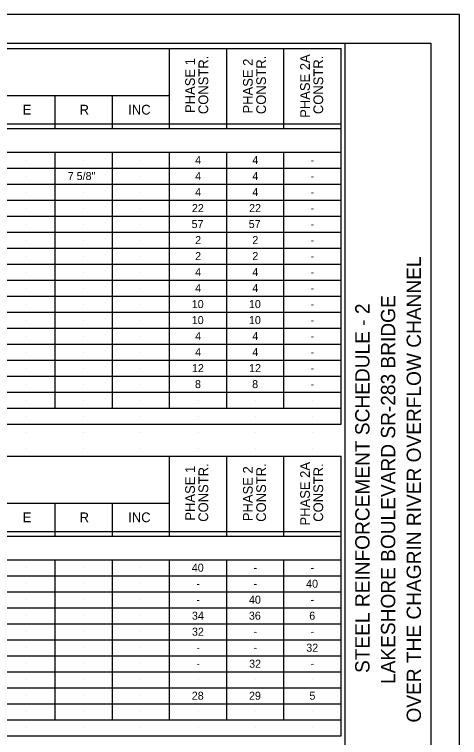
# Model space of a CAD drawing. Extents: x 0 to 34, y 0 to 22.
# Drawn here: x 26.21 to 34, y 9.35 to 22 of the extents above; entities that cross this region are included whole.
import ezdxf

# ---------------------------------------------------------------- set-up
doc = ezdxf.new("R2010")
doc.units = 0
for name, color, linetype in [('BR_P_Gen_Text', 7, 'Continuous'), ('SH_Border', 7, 'Continuous'), ('SH_Cut_Line', 7, 'Continuous'), ('SH_Data', 7, 'Continuous')]:
    doc.layers.add(name, color=color, linetype=linetype)

msp = doc.modelspace()

# ---------------------------------------------------------------- linework, layer by layer
at = {"layer": 'BR_P_Gen_Text'}
for p, q in [((16.76, 21.404), (31.927, 21.404)), ((28.927, 20.004), (28.927, 21.404)), ((29.927, 20.004), (29.927, 21.404)), ((30.927, 20.004), (30.927, 21.404)), ((31.927, 14.833), (31.927, 21.404)), ((21.927, 20.581), (28.927, 20.581)), ((26.927, 20.004), (26.927, 20.581)), ((27.927, 20.004), (27.927, 20.581)), ((16.76, 20.087), (31.927, 20.087)), ((16.76, 20.004), (31.927, 20.004)), ((16.76, 19.593), (31.927, 19.593)), ((26.927, 15.113), (26.927, 19.593)), ((27.927, 15.113), (27.927, 19.593)), ((28.927, 15.113), (28.927, 19.593)), ((29.927, 15.113), (29.927, 19.593)), ((30.927, 15.113), (30.927, 19.593)), ((26.427, 19.453), (26.427, 19.453)), ((27.427, 19.453), (27.427, 19.453)), ((28.427, 19.453), (28.427, 19.453)), ((29.427, 19.453), (29.427, 19.453)), ((30.427, 19.453), (30.427, 19.453)), ((31.427, 19.453), (31.427, 19.453)), ((16.76, 19.313), (31.927, 19.313)), ((26.427, 19.173), (26.427, 19.173)), ((27.427, 19.173), (27.427, 19.173)), ((28.427, 19.173), (28.427, 19.173)), ((29.427, 19.173), (29.427, 19.173)), ((30.427, 19.173), (30.427, 19.173)), ((31.427, 19.173), (31.427, 19.173)), ((16.76, 19.033), (31.927, 19.033)), ((26.427, 18.893), (26.427, 18.893)), ((27.427, 18.893), (27.427, 18.893)), ((28.427, 18.893), (28.427, 18.893)), ((29.427, 18.893), (29.427, 18.893)), ((30.427, 18.893), (30.427, 18.893)), ((31.427, 18.893), (31.427, 18.893)), ((16.76, 18.753), (31.927, 18.753)), ((26.427, 18.613), (26.427, 18.613)), ((27.427, 18.613), (27.427, 18.613)), ((28.427, 18.613), (28.427, 18.613)), ((29.427, 18.613), (29.427, 18.613)), ((30.427, 18.613), (30.427, 18.613)), ((31.427, 18.613), (31.427, 18.613)), ((16.76, 18.473), (31.927, 18.473)), ((26.427, 18.333), (26.427, 18.333)), ((27.427, 18.333), (27.427, 18.333)), ((28.427, 18.333), (28.427, 18.333)), ((29.427, 18.333), (29.427, 18.333)), ((30.427, 18.333), (30.427, 18.333)), ((31.427, 18.333), (31.427, 18.333)), ((16.76, 18.193), (31.927, 18.193)), ((26.427, 18.053), (26.427, 18.053)), ((27.427, 18.053), (27.427, 18.053)), ((28.427, 18.053), (28.427, 18.053)), ((29.427, 18.053), (29.427, 18.053)), ((30.427, 18.053), (30.427, 18.053)), ((31.427, 18.053), (31.427, 18.053)), ((16.76, 17.913), (31.927, 17.913)), ((26.427, 17.773), (26.427, 17.773)), ((27.427, 17.773), (27.427, 17.773)), ((28.427, 17.773), (28.427, 17.773)), ((29.427, 17.773), (29.427, 17.773)), ((30.427, 17.773), (30.427, 17.773)), ((31.427, 17.773), (31.427, 17.773)), ((16.76, 17.633), (31.927, 17.633)), ((26.427, 17.493), (26.427, 17.493)), ((26.427, 17.493), (26.427, 17.493)), ((27.427, 17.493), (27.427, 17.493)), ((27.427, 17.493), (27.427, 17.493)), ((28.427, 17.493), (28.427, 17.493)), ((28.427, 17.493), (28.427, 17.493)), ((29.427, 17.493), (29.427, 17.493)), ((30.427, 17.493), (30.427, 17.493)), ((31.427, 17.493), (31.427, 17.493)), ((16.76, 17.353), (31.927, 17.353)), ((26.427, 17.213), (26.427, 17.213)), ((26.427, 17.213), (26.427, 17.213)), ((27.427, 17.213), (27.427, 17.213)), ((27.427, 17.213), (27.427, 17.213)), ((28.427, 17.213), (28.427, 17.213)), ((28.427, 17.213), (28.427, 17.213)), ((29.427, 17.213), (29.427, 17.213)), ((29.427, 17.213), (29.427, 17.213)), ((30.427, 17.213), (30.427, 17.213)), ((30.427, 17.213), (30.427, 17.213)), ((31.427, 17.213), (31.427, 17.213)), ((31.427, 17.213), (31.427, 17.213)), ((16.76, 17.073), (31.927, 17.073)), ((26.427, 16.933), (26.427, 16.933)), ((27.427, 16.933), (27.427, 16.933)), ((28.427, 16.933), (28.427, 16.933)), ((29.427, 16.933), (29.427, 16.933)), ((30.427, 16.933), (30.427, 16.933)), ((31.427, 16.933), (31.427, 16.933)), ((16.76, 16.793), (31.927, 16.793)), ((26.427, 16.653), (26.427, 16.653)), ((27.427, 16.653), (27.427, 16.653)), ((28.427, 16.653), (28.427, 16.653)), ((29.427, 16.653), (29.427, 16.653)), ((30.427, 16.653), (30.427, 16.653)), ((31.427, 16.653), (31.427, 16.653)), ((16.76, 16.513), (31.927, 16.513)), ((26.427, 16.373), (26.427, 16.373)), ((27.427, 16.373), (27.427, 16.373)), ((28.427, 16.373), (28.427, 16.373)), ((29.427, 16.373), (29.427, 16.373)), ((30.427, 16.373), (30.427, 16.373)), ((31.427, 16.373), (31.427, 16.373)), ((16.76, 16.233), (31.927, 16.233)), ((26.427, 16.093), (26.427, 16.093)), ((27.427, 16.093), (27.427, 16.093)), ((28.427, 16.093), (28.427, 16.093)), ((29.427, 16.093), (29.427, 16.093)), ((30.427, 16.093), (30.427, 16.093)), ((31.427, 16.093), (31.427, 16.093)), ((16.76, 15.953), (31.927, 15.953)), ((26.427, 15.813), (26.427, 15.813)), ((27.427, 15.813), (27.427, 15.813)), ((28.427, 15.813), (28.427, 15.813)), ((29.427, 15.813), (29.427, 15.813)), ((30.427, 15.813), (30.427, 15.813)), ((31.427, 15.813), (31.427, 15.813)), ((16.76, 15.673), (31.927, 15.673)), ((26.427, 15.533), (26.427, 15.533)), ((27.427, 15.533), (27.427, 15.533)), ((28.427, 15.533), (28.427, 15.533)), ((29.427, 15.533), (29.427, 15.533)), ((30.427, 15.533), (30.427, 15.533)), ((31.427, 15.533), (31.427, 15.533)), ((16.76, 15.393), (31.927, 15.393)), ((26.427, 15.253), (26.427, 15.253)), ((27.427, 15.253), (27.427, 15.253)), ((28.427, 15.253), (28.427, 15.253)), ((29.427, 15.253), (29.427, 15.253)), ((30.427, 15.253), (30.427, 15.253)), ((31.427, 15.253), (31.427, 15.253)), ((16.76, 15.113), (31.927, 15.113)), ((26.427, 14.973), (26.427, 14.973)), ((27.427, 14.973), (27.427, 14.973)), ((28.427, 14.973), (28.427, 14.973)), ((29.427, 14.973), (29.427, 14.973)), ((30.427, 14.973), (30.427, 14.973)), ((31.427, 14.973), (31.427, 14.973)), ((16.76, 14.833), (31.927, 14.833)), ((26.427, 14.693), (26.427, 14.693)), ((26.427, 14.693), (26.427, 14.693)), ((27.427, 14.693), (27.427, 14.693)), ((27.427, 14.693), (27.427, 14.693)), ((28.427, 14.693), (28.427, 14.693)), ((28.427, 14.693), (28.427, 14.693)), ((29.427, 14.693), (29.427, 14.693)), ((30.427, 14.693), (30.427, 14.693)), ((31.427, 14.693), (31.427, 14.693)), ((26.427, 14.413), (26.427, 14.413)), ((27.427, 14.413), (27.427, 14.413)), ((28.427, 14.413), (28.427, 14.413)), ((29.427, 14.413), (29.427, 14.413)), ((30.427, 14.413), (30.427, 14.413)), ((31.427, 14.413), (31.427, 14.413)), ((16.76, 14.272), (31.927, 14.273)), ((28.927, 12.872), (28.927, 14.273)), ((29.927, 12.872), (29.927, 14.273)), ((30.927, 12.872), (30.927, 14.273)), ((31.927, 9.381), (31.927, 14.273)), ((21.927, 13.449), (28.927, 13.449)), ((26.927, 12.872), (26.927, 13.449)), ((27.927, 12.872), (27.927, 13.449)), ((16.76, 12.955), (31.927, 12.955)), ((16.76, 12.872), (31.927, 12.872)), ((16.76, 12.461), (31.927, 12.461)), ((26.927, 9.661), (26.927, 12.461)), ((27.927, 9.661), (27.927, 12.461)), ((28.927, 9.661), (28.927, 12.461)), ((29.927, 9.661), (29.927, 12.461)), ((30.927, 9.661), (30.927, 12.461)), ((26.427, 12.321), (26.427, 12.321)), ((27.427, 12.321), (27.427, 12.321)), ((28.427, 12.321), (28.427, 12.321)), ((29.427, 12.321), (29.427, 12.321)), ((30.427, 12.321), (30.427, 12.321)), ((31.427, 12.321), (31.427, 12.321)), ((16.76, 12.181), (31.927, 12.181)), ((26.427, 12.041), (26.427, 12.041)), ((27.427, 12.041), (27.427, 12.041)), ((28.427, 12.041), (28.427, 12.041)), ((29.427, 12.041), (29.427, 12.041)), ((30.427, 12.041), (30.427, 12.041)), ((31.427, 12.041), (31.427, 12.041)), ((16.76, 11.901), (31.927, 11.901)), ((26.427, 11.761), (26.427, 11.761)), ((27.427, 11.761), (27.427, 11.761)), ((28.427, 11.761), (28.427, 11.761)), ((30.427, 11.761), (30.427, 11.761)), ((31.427, 11.761), (31.427, 11.761)), ((16.76, 11.621), (31.927, 11.621)), ((26.427, 11.481), (26.427, 11.481)), ((27.427, 11.481), (27.427, 11.481)), ((28.427, 11.481), (28.427, 11.481)), ((29.427, 11.481), (29.427, 11.481)), ((30.427, 11.481), (30.427, 11.481)), ((31.427, 11.481), (31.427, 11.481)), ((16.76, 11.341), (31.927, 11.341)), ((26.427, 11.201), (26.427, 11.201)), ((27.427, 11.201), (27.427, 11.201)), ((28.427, 11.201), (28.427, 11.201)), ((29.427, 11.201), (29.427, 11.201)), ((30.427, 11.201), (30.427, 11.201)), ((31.427, 11.201), (31.427, 11.201)), ((16.76, 11.061), (31.927, 11.061)), ((26.427, 10.921), (26.427, 10.921)), ((27.427, 10.921), (27.427, 10.921)), ((28.427, 10.921), (28.427, 10.921)), ((29.427, 10.921), (29.427, 10.921)), ((30.427, 10.921), (30.427, 10.921)), ((31.427, 10.921), (31.427, 10.921)), ((16.76, 10.781), (31.927, 10.781)), ((26.427, 10.641), (26.427, 10.641)), ((27.427, 10.641), (27.427, 10.641)), ((28.427, 10.641), (28.427, 10.641)), ((29.427, 10.641), (29.427, 10.641)), ((30.427, 10.641), (30.427, 10.641)), ((31.427, 10.641), (31.427, 10.641)), ((16.76, 10.501), (31.927, 10.501)), ((26.427, 10.361), (26.427, 10.361)), ((26.427, 10.361), (26.427, 10.361)), ((27.427, 10.361), (27.427, 10.361)), ((27.427, 10.361), (27.427, 10.361)), ((28.427, 10.361), (28.427, 10.361)), ((28.427, 10.361), (28.427, 10.361)), ((29.427, 10.361), (29.427, 10.361)), ((30.427, 10.361), (30.427, 10.361)), ((31.427, 10.361), (31.427, 10.361)), ((16.76, 10.221), (31.927, 10.221)), ((26.427, 10.081), (26.427, 10.081)), ((26.427, 10.081), (26.427, 10.081)), ((27.427, 10.081), (27.427, 10.081)), ((27.427, 10.081), (27.427, 10.081)), ((28.427, 10.081), (28.427, 10.081)), ((28.427, 10.081), (28.427, 10.081)), ((29.427, 10.081), (29.427, 10.081)), ((29.427, 10.081), (29.427, 10.081)), ((30.427, 10.081), (30.427, 10.081)), ((30.427, 10.081), (30.427, 10.081)), ((31.427, 10.081), (31.427, 10.081)), ((31.427, 10.081), (31.427, 10.081)), ((16.76, 9.941), (31.927, 9.941)), ((26.427, 9.801), (26.427, 9.801)), ((27.427, 9.801), (27.427, 9.801)), ((28.427, 9.801), (28.427, 9.801)), ((29.427, 9.801), (29.427, 9.801)), ((30.427, 9.801), (30.427, 9.801)), ((31.427, 9.801), (31.427, 9.801)), ((16.76, 9.661), (31.927, 9.661)), ((26.427, 9.521), (26.427, 9.521)), ((27.427, 9.521), (27.427, 9.521)), ((28.427, 9.521), (28.427, 9.521)), ((29.427, 9.521), (29.427, 9.521)), ((30.427, 9.521), (30.427, 9.521)), ((31.427, 9.521), (31.427, 9.521)), ((16.76, 9.381), (31.927, 9.381))]:
    msp.add_line(p, q, dxfattribs=at)
at = {"layer": 'SH_Border'}
msp.add_line((32, 0.5), (32, 21.5), dxfattribs=at)
msp.add_lwpolyline([(1.5, 21.5), (33.5, 21.5), (33.5, 0.5), (1.5, 0.5)], close=True, dxfattribs=at)
at = {"layer": 'SH_Cut_Line'}
msp.add_lwpolyline([(0, 0), (34, 0), (34, 22), (0, 22)], close=True, dxfattribs=at)

# ---------------------------------------------------------------- texts
at = {"layer": 'BR_P_Gen_Text'}
for s, p in [('CONSTR.', (29.603, 20.256)), ('CONSTR.', (30.614, 20.256)), ('PHASE 2A', (31.382, 20.191)), ('CONSTR.', (31.614, 20.256)), ('PHASE 1', (29.371, 20.276)), ('PHASE 2', (30.382, 20.267)), ('PHASE 2A', (31.382, 13.059)), ('PHASE 1', (29.371, 13.144)), ('CONSTR.', (29.603, 13.124)), ('PHASE 2', (30.382, 13.135)), ('CONSTR.', (30.614, 13.124)), ('CONSTR.', (31.614, 13.124))]:
    msp.add_text(s, height=0.17, rotation=90, dxfattribs=at).set_placement(p)
for s, height, p in [('E', 0.17, (26.358, 20.249)), ('R', 0.17, (27.354, 20.249)), ('INC', 0.17, (28.204, 20.249)), ('4', 0.14, (29.375, 19.383)), ('4', 0.14, (30.375, 19.383)), ('-', 0.14, (31.396, 19.383)), ('7 5/8"', 0.14, (27.146, 19.103)), ('4', 0.14, (29.375, 19.103)), ('4', 0.14, (30.375, 19.103)), ('-', 0.14, (31.396, 19.103)), ('4', 0.14, (29.375, 18.823)), ('4', 0.14, (30.375, 18.823)), ('-', 0.14, (31.396, 18.823)), ('22', 0.14, (29.319, 18.543)), ('22', 0.14, (30.319, 18.543)), ('-', 0.14, (31.396, 18.543)), ('57', 0.14, (29.312, 18.263)), ('57', 0.14, (30.312, 18.263)), ('-', 0.14, (31.396, 18.263)), ('2', 0.14, (29.375, 17.983)), ('2', 0.14, (30.375, 17.983)), ('-', 0.14, (31.396, 17.983)), ('2', 0.14, (29.375, 17.703)), ('2', 0.14, (30.375, 17.703)), ('-', 0.14, (31.396, 17.703)), ('4', 0.14, (29.375, 17.423)), ('4', 0.14, (30.375, 17.423)), ('-', 0.14, (31.396, 17.423)), ('4', 0.14, (29.375, 17.143)), ('4', 0.14, (30.375, 17.143)), ('-', 0.14, (31.396, 17.143)), ('10', 0.14, (29.316, 16.863)), ('10', 0.14, (30.316, 16.863)), ('-', 0.14, (31.396, 16.863)), ('10', 0.14, (29.316, 16.583)), ('10', 0.14, (30.316, 16.583)), ('-', 0.14, (31.396, 16.583)), ('4', 0.14, (29.375, 16.303)), ('4', 0.14, (30.375, 16.303)), ('-', 0.14, (31.396, 16.303)), ('4', 0.14, (29.375, 16.023)), ('4', 0.14, (30.375, 16.023)), ('-', 0.14, (31.396, 16.023)), ('12', 0.14, (29.319, 15.743)), ('12', 0.14, (30.319, 15.743)), ('-', 0.14, (31.396, 15.743)), ('8', 0.14, (29.372, 15.463)), ('8', 0.14, (30.372, 15.463)), ('-', 0.14, (31.396, 15.463)), ('E', 0.17, (26.358, 13.117)), ('R', 0.17, (27.354, 13.117)), ('INC', 0.17, (28.204, 13.117)), ('40', 0.14, (29.316, 12.251)), ('-', 0.14, (30.396, 12.251)), ('-', 0.14, (31.396, 12.251)), ('-', 0.14, (29.396, 11.971)), ('-', 0.14, (30.396, 11.971)), ('40', 0.14, (31.316, 11.971)), ('40', 0.14, (30.316, 11.691)), ('-', 0.14, (29.396, 11.691)), ('-', 0.14, (31.396, 11.691)), ('34', 0.14, (29.319, 11.411)), ('36', 0.14, (30.315, 11.411)), ('6', 0.14, (31.371, 11.411)), ('32', 0.14, (29.319, 11.131)), ('-', 0.14, (30.396, 11.131)), ('-', 0.14, (31.396, 11.131)), ('-', 0.14, (29.396, 10.851)), ('-', 0.14, (30.396, 10.851)), ('32', 0.14, (31.319, 10.851)), ('-', 0.14, (29.396, 10.571)), ('32', 0.14, (30.319, 10.571)), ('-', 0.14, (31.396, 10.571)), ('28', 0.14, (29.316, 10.011)), ('29', 0.14, (30.317, 10.011)), ('5', 0.14, (31.374, 10.011))]:
    msp.add_text(s, height=height, dxfattribs=at).set_placement(p)
at = {"layer": 'SH_Data'}
for s, p in [('OVER THE CHAGRIN RIVER OVERFLOW CHANNEL', (33.325, 9.612)), ('LAKESHORE BOULEVARD SR-283 BRIDGE', (32.875, 10.287)), ('STEEL REINFORCEMENT SCHEDULE - 2', (32.425, 10.479))]:
    msp.add_text(s, height=0.25, rotation=90, dxfattribs=at).set_placement(p)

doc.saveas('drawing.dxf')
